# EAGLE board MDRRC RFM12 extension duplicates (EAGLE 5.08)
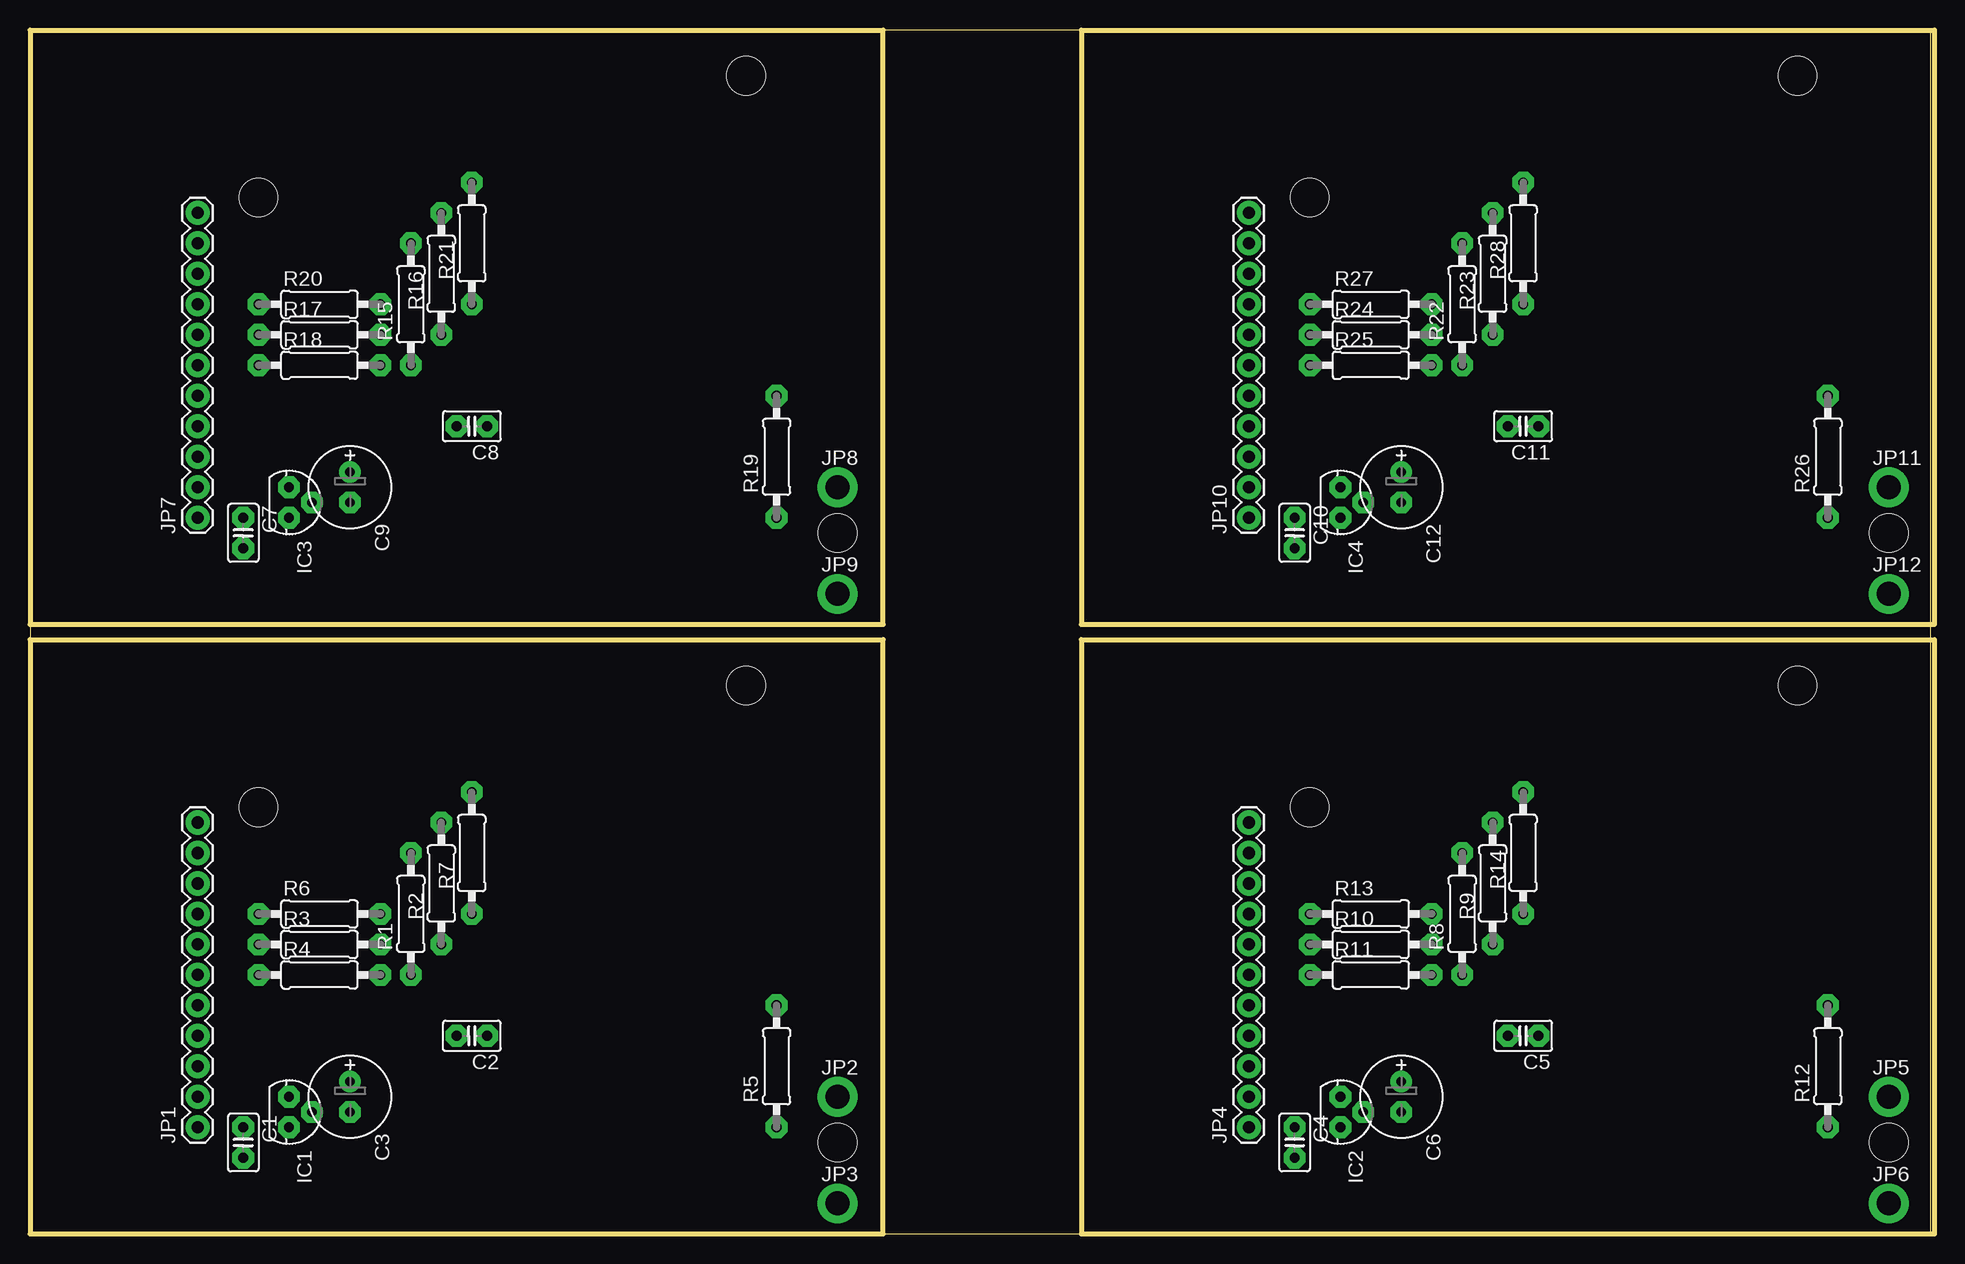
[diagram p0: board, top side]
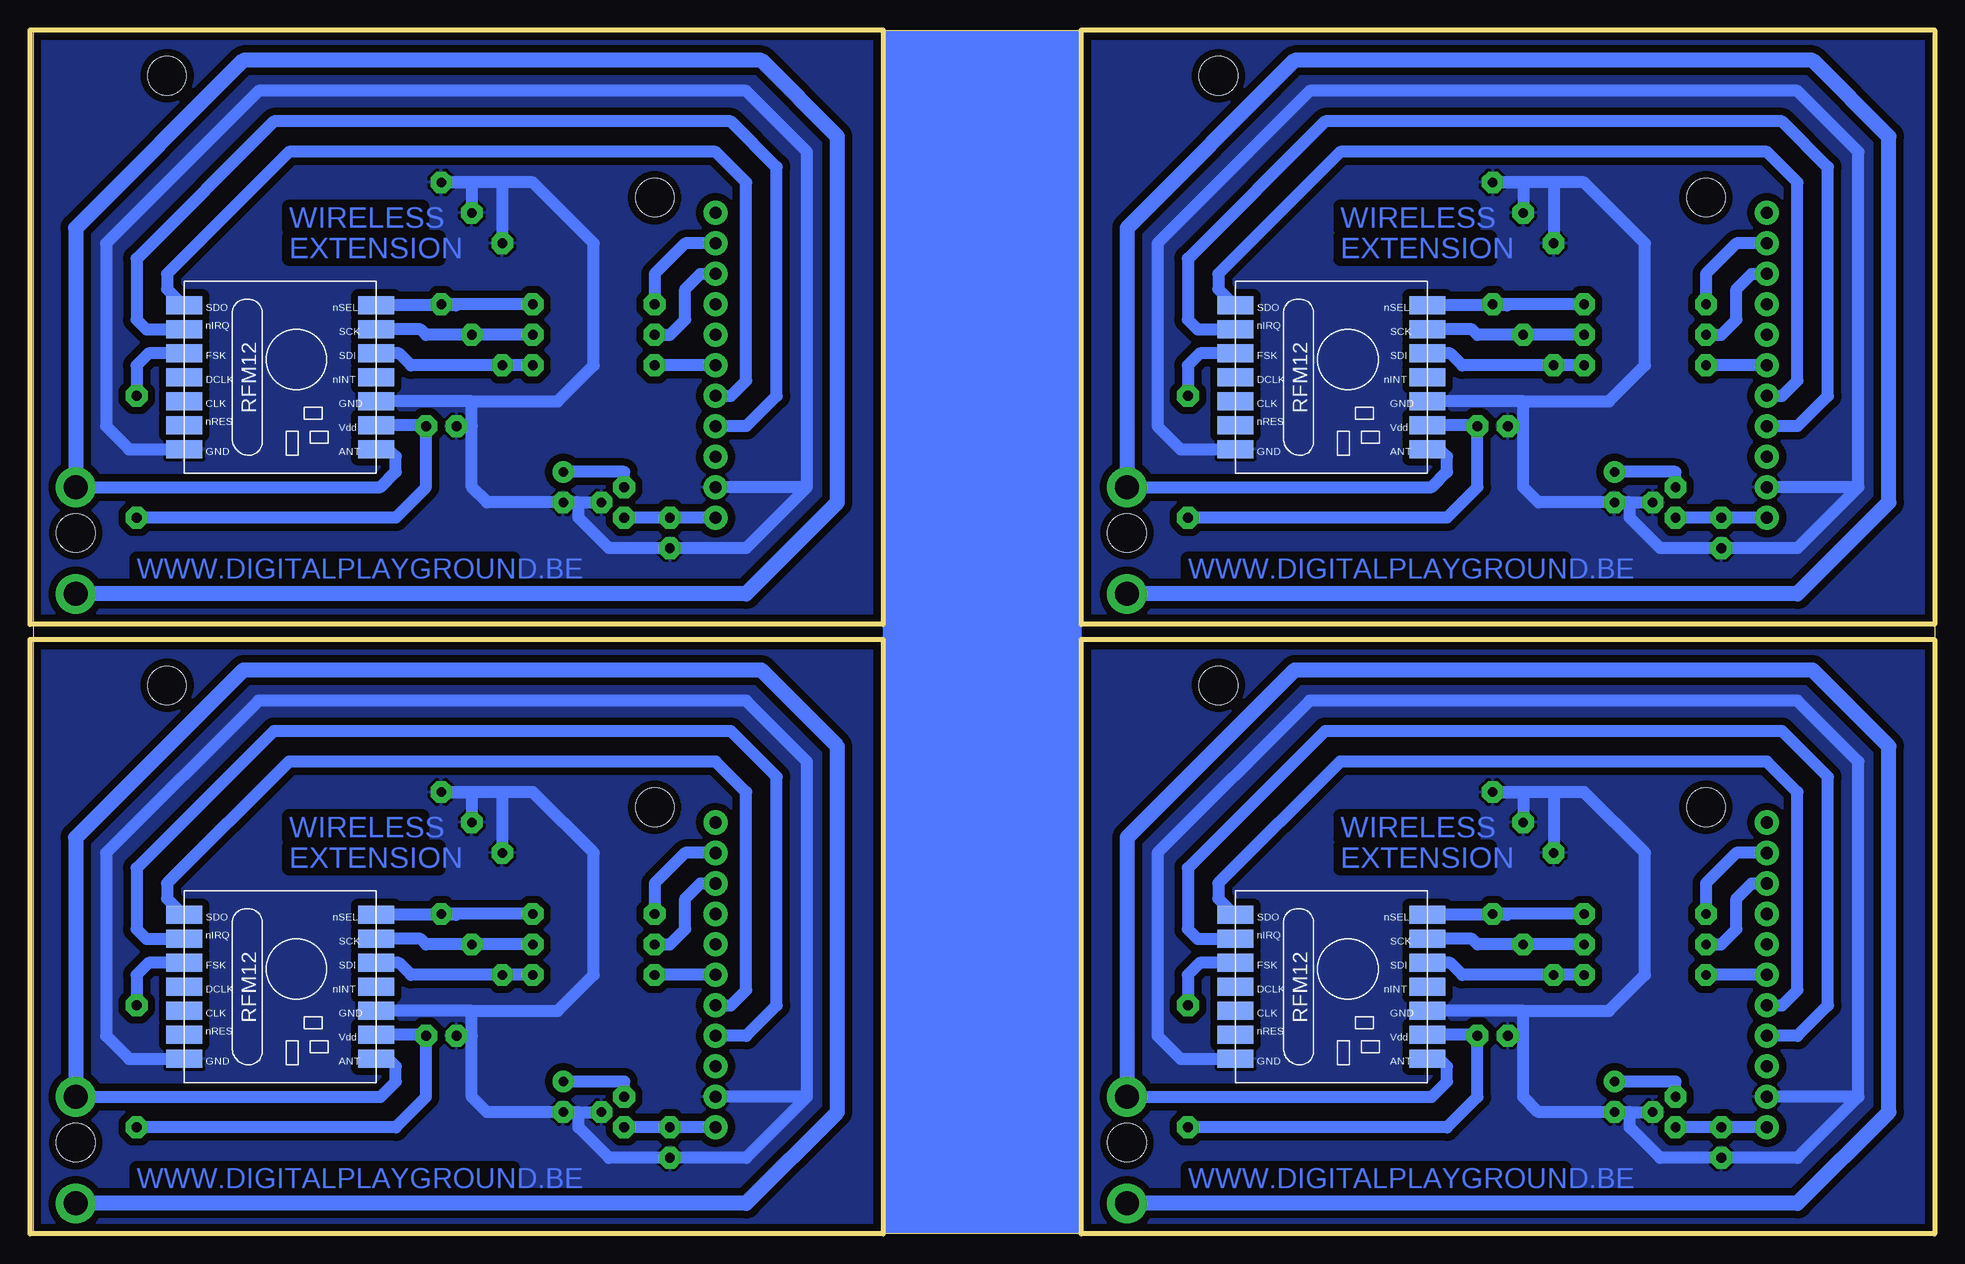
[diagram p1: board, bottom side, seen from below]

Size 158.75 x 100.33 mm. Coordinates in mm from the lower left corner, seen from the top.
Outline: 71.12,0 87.63,0
Outline: 87.63,0 158.42,0 158.42,100.32 0,100.32 0,0
Outline: 0,0 0,49.53 71.12,49.53 71.12,0
Outline: 0,0 71.12,0
Outline: 87.63,0 87.63,49.53 158.75,49.53 158.75,0 87.63,0
Outline: 0,100.33 0,50.8 71.12,50.8 71.12,100.33 0,100.33
Outline: 87.63,100.33 87.63,50.8 158.75,50.8 158.75,100.33 87.63,100.33
Copper layers (1*16): Top 0.8mm / dielectric 1.3mm / Bottom 0.8mm
Design rules "DRC settings smallest": minimum track width 0.8mm, minimum drill 24mil, track to track 0.2mm, track to pad 0.2mm, pad to pad 0.2mm, via to via 0.2mm, smd to smd 8mil, copper to edge 0.3mm, drill to drill 0.3mm, minimum pad ring 0.5mm, minimum via ring 1mm, stop-mask expansion 4mil, vias tented up to drill 0mil, thermal gap 10mil
Holes 3.2 mm at 59.69,45.72 67.31,7.62 19.05,35.56 147.32,45.72 154.94,7.62 106.68,35.56 59.69,96.52 67.31,58.42 19.05,86.36 147.32,96.52 154.94,58.42 106.68,86.36

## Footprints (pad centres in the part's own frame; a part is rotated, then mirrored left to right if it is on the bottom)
C025-025X050 = drill 0.813 octagon: 1 -1.27,0; 2 1.27,0
E2,5-7 = drill 0.813 pad 1.6 round: + -1.27,0 | drill 0.813 pad 1.6 octagon: - 1.27,0
78LXX = drill 0.813 octagon: GND 0,1.905; IN 1.27,0; OUT -1.27,0
1X11 = drill 1.016 pad 1.88 round: 1 0,0; 2 2.54,0; 3 5.08,0; 4 7.62,0; 5 10.16,0; 6 12.7,0; 7 15.24,0; 8 17.78,0; 9 20.32,0; 10 22.86,0; 11 25.4,0
1X01_2MM = drill 2 pad 3.302 round: 1 0,0
0207/10 = drill 0.813 octagon: 1 -5.08,0; 2 5.08,0
RFM12 = smd 1.5 x 3: 1 -5,-10; 2 -3,-10; 3 -1,-10; 4 1,-10; 5 3,-10; 6 5,-10; 7 7,-10; 8 7,6; 9 5,6; 10 3,6; 11 1,6; 12 -1,6; 13 -3,6; 14 -5,6

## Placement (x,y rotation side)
C1  100nF  [C025-025X050]  17.78,7.62 270 top
C2  100nF  [C025-025X050]  36.83,16.51 180 top
C3  10uF  [E2,5-7]  26.67,11.43 270 top
C4  100nF  [C025-025X050]  105.41,7.62 270 top
C5  100nF  [C025-025X050]  124.46,16.51 180 top
C6  10uF  [E2,5-7]  114.3,11.43 270 top
C7  100nF  [C025-025X050]  17.78,58.42 270 top
C8  100nF  [C025-025X050]  36.83,67.31 180 top
C9  10uF  [E2,5-7]  26.67,62.23 270 top
C10  100nF  [C025-025X050]  105.41,58.42 270 top
C11  100nF  [C025-025X050]  124.46,67.31 180 top
C12  10uF  [E2,5-7]  114.3,62.23 270 top
IC1  78L33  [78LXX]  21.59,10.16 270 top
IC2  78L33  [78LXX]  109.22,10.16 270 top
IC3  78L33  [78LXX]  21.59,60.96 270 top
IC4  78L33  [78LXX]  109.22,60.96 270 top
JP1  M11PTH  [1X11]  13.97,8.89 90 top
JP2  M01PTH_2MM  [1X01_2MM]  67.31,11.43 0 top
JP3  M01PTH_2MM  [1X01_2MM]  67.31,2.54 0 top
JP4  M11PTH  [1X11]  101.6,8.89 90 top
JP5  M01PTH_2MM  [1X01_2MM]  154.94,11.43 0 top
JP6  M01PTH_2MM  [1X01_2MM]  154.94,2.54 0 top
JP7  M11PTH  [1X11]  13.97,59.69 90 top
JP8  M01PTH_2MM  [1X01_2MM]  67.31,62.23 0 top
JP9  M01PTH_2MM  [1X01_2MM]  67.31,53.34 0 top
JP10  M11PTH  [1X11]  101.6,59.69 90 top
JP11  M01PTH_2MM  [1X01_2MM]  154.94,62.23 0 top
JP12  M01PTH_2MM  [1X01_2MM]  154.94,53.34 0 top
R1  2K2  [0207/10]  31.75,26.67 90 top
R2  2K2  [0207/10]  34.29,29.21 90 top
R3  1K  [0207/10]  24.13,24.13 0 top
R4  1K  [0207/10]  24.13,21.59 0 top
R5  10K  [0207/10]  62.23,13.97 90 top
R6  1K  [0207/10]  24.13,26.67 0 top
R7  2K2  [0207/10]  36.83,31.75 90 top
R8  2K2  [0207/10]  119.38,26.67 90 top
R9  2K2  [0207/10]  121.92,29.21 90 top
R10  1K  [0207/10]  111.76,24.13 0 top
R11  1K  [0207/10]  111.76,21.59 0 top
R12  10K  [0207/10]  149.86,13.97 90 top
R13  1K  [0207/10]  111.76,26.67 0 top
R14  2K2  [0207/10]  124.46,31.75 90 top
R15  2K2  [0207/10]  31.75,77.47 90 top
R16  2K2  [0207/10]  34.29,80.01 90 top
R17  1K  [0207/10]  24.13,74.93 0 top
R18  1K  [0207/10]  24.13,72.39 0 top
R19  10K  [0207/10]  62.23,64.77 90 top
R20  1K  [0207/10]  24.13,77.47 0 top
R21  2K2  [0207/10]  36.83,82.55 90 top
R22  2K2  [0207/10]  119.38,77.47 90 top
R23  2K2  [0207/10]  121.92,80.01 90 top
R24  1K  [0207/10]  111.76,74.93 0 top
R25  1K  [0207/10]  111.76,72.39 0 top
R26  10K  [0207/10]  149.86,64.77 90 top
R27  1K  [0207/10]  111.76,77.47 0 top
R28  2K2  [0207/10]  124.46,82.55 90 top
U$1  RFM12_SMDSMD  [RFM12]  48.26,21.59 270 bottom
U$2  RFM12_SMDSMD  [RFM12]  135.89,21.59 270 bottom
U$3  RFM12_SMDSMD  [RFM12]  48.26,72.39 270 bottom
U$4  RFM12_SMDSMD  [RFM12]  135.89,72.39 270 bottom

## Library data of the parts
C1 C2 C4 C5 C7 C8 C10 C11 = rcl
C3 C6 C9 C12 R1-R28 = resistor
IC1-IC4 = v-reg
JP1-JP12 = SparkFun
U$1-U$4 = rfm_12

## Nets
+3V1: C6.+ IC2.OUT
+3V2: C9.+ IC3.OUT
+3V3: C3.+ IC1.OUT
+3V4: C12.+ IC4.OUT
+5V: C1.1 IC1.IN JP1.1
+5V1: C4.1 IC2.IN JP4.1
+5V2: C7.1 IC3.IN JP7.1
+5V3: C10.1 IC4.IN JP10.1
GND: C1.2 C2.2 C3.- IC1.GND JP1.2 R1.2 R2.2 R7.2 U$1.7 U$1.10
GND1: C4.2 C5.2 C6.- IC2.GND JP4.2 R8.2 R9.2 R14.2 U$2.7 U$2.10
GND2: C7.2 C8.2 C9.- IC3.GND JP7.2 R15.2 R16.2 R21.2 U$3.7 U$3.10
GND3: C10.2 C11.2 C12.- IC4.GND JP10.2 R22.2 R23.2 R28.2 U$4.7 U$4.10
N$1: JP2.1 JP3.1 U$1.8
N$2: JP1.10 R6.1
N$3: R5.2 U$1.3
N$4: R2.1 R3.2 U$1.13
N$5: R1.1 R4.2 U$1.12
N$6: R6.2 R7.1 U$1.14
N$7: JP1.4 U$1.2
N$8: JP1.9 R3.1
N$9: JP1.6 R4.1
N$10: JP1.5 U$1.1
N$11: JP5.1 JP6.1 U$2.8
N$12: R12.2 U$2.3
N$13: R9.1 R10.2 U$2.13
N$14: R8.1 R11.2 U$2.12
N$15: R13.2 R14.1 U$2.14
N$16: JP4.4 U$2.2
N$17: JP4.10 R13.1
N$18: JP4.9 R10.1
N$19: JP4.6 R11.1
N$20: JP4.5 U$2.1
N$21: JP8.1 JP9.1 U$3.8
N$22: R19.2 U$3.3
N$23: R16.1 R17.2 U$3.13
N$24: R15.1 R18.2 U$3.12
N$25: R20.2 R21.1 U$3.14
N$26: JP7.4 U$3.2
N$27: JP7.10 R20.1
N$28: JP7.9 R17.1
N$29: JP7.6 R18.1
N$30: JP7.5 U$3.1
N$31: JP11.1 JP12.1 U$4.8
N$32: R26.2 U$4.3
N$33: R23.1 R24.2 U$4.13
N$34: R22.1 R25.2 U$4.12
N$35: R27.2 R28.1 U$4.14
N$36: JP10.4 U$4.2
N$37: JP10.10 R27.1
N$38: JP10.9 R24.1
N$39: JP10.6 R25.1
N$40: JP10.5 U$4.1
VDD: C2.1 R5.1 U$1.9
VDD1: C5.1 R12.1 U$2.9
VDD2: C8.1 R19.1 U$3.9
VDD3: C11.1 R26.1 U$4.9

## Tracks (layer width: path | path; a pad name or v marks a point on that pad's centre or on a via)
+3V1
  Bottom 1.016: C6.+ 109.22,12.7 IC2.OUT
+3V2
  Bottom 1.016: C9.+ 21.59,63.5 IC3.OUT
+3V3
  Bottom 1.016: C3.+ 21.59,12.7 IC1.OUT
+3V4
  Bottom 1.016: C12.+ 109.22,63.5 IC4.OUT
+5V
  Bottom 1.016: IC1.IN C1.1 JP1.1
+5V1
  Bottom 1.016: IC2.IN C4.1 JP4.1
+5V2
  Bottom 1.016: IC3.IN C7.1 JP7.1
+5V3
  Bottom 1.016: IC4.IN C10.1 JP10.1
GND
  Bottom 1.016: 57.77,14.59 U$1.7 62.85,14.59 64.77,16.51 64.77,31.75 52.07,44.45 11.43,44.45 6.35,39.37 6.35,11.43 | 25.4,10.16 IC1.GND | 25.4,10.16 C3.- 33.02,10.16 34.29,11.43 34.29,16.51 | R2.2 34.29,36.83 R7.2 31.75,36.83 | 31.75,36.83 R1.2 | 34.29,16.51 C2.2 | 6.35,11.43 11.43,6.35 C1.2 22.86,6.35 25.4,8.89 25.4,10.16 | 6.35,11.43 JP1.2 | 31.75,36.83 29.21,36.83 24.13,31.75 24.13,21.59 27.13,18.59 34.29,18.59 | 34.29,18.59 U$1.10 | 34.29,16.51 34.29,18.59
  pour Bottom (isolate 0.61): 0,49.53 71.12,49.53 71.12,0 0,0
GND1
  Bottom 1.016: 145.4,14.59 U$2.7 150.48,14.59 152.4,16.51 152.4,31.75 139.7,44.45 99.06,44.45 93.98,39.37 93.98,11.43 | 113.03,10.16 IC2.GND | 113.03,10.16 C6.- 120.65,10.16 121.92,11.43 121.92,16.51 | R9.2 121.92,36.83 R14.2 119.38,36.83 | 119.38,36.83 R8.2 | 121.92,16.51 C5.2 | 93.98,11.43 99.06,6.35 C4.2 110.49,6.35 113.03,8.89 113.03,10.16 | 93.98,11.43 JP4.2 | 119.38,36.83 116.84,36.83 111.76,31.75 111.76,21.59 114.76,18.59 121.92,18.59 | 121.92,18.59 U$2.10 | 121.92,16.51 121.92,18.59
  pour Bottom (isolate 0.61): 87.63,49.53 158.75,49.53 158.75,0 87.63,0
GND2
  Bottom 1.016: 57.77,65.39 U$3.7 62.85,65.39 64.77,67.31 64.77,82.55 52.07,95.25 11.43,95.25 6.35,90.17 6.35,62.23 | 25.4,60.96 IC3.GND | 25.4,60.96 C9.- 33.02,60.96 34.29,62.23 34.29,67.31 | R16.2 34.29,87.63 R21.2 31.75,87.63 | 31.75,87.63 R15.2 | 34.29,67.31 C8.2 | 6.35,62.23 11.43,57.15 C7.2 22.86,57.15 25.4,59.69 25.4,60.96 | 6.35,62.23 JP7.2 | 31.75,87.63 29.21,87.63 24.13,82.55 24.13,72.39 27.13,69.39 34.29,69.39 | 34.29,69.39 U$3.10 | 34.29,67.31 34.29,69.39
  pour Bottom (isolate 0.61): 0,100.33 71.12,100.33 71.12,50.8 0,50.8
GND3
  Bottom 1.016: 145.4,65.39 U$4.7 150.48,65.39 152.4,67.31 152.4,82.55 139.7,95.25 99.06,95.25 93.98,90.17 93.98,62.23 | 113.03,60.96 IC4.GND | 113.03,60.96 C12.- 120.65,60.96 121.92,62.23 121.92,67.31 | R23.2 121.92,87.63 R28.2 119.38,87.63 | 119.38,87.63 R22.2 | 121.92,67.31 C11.2 | 93.98,62.23 99.06,57.15 C10.2 110.49,57.15 113.03,59.69 113.03,60.96 | 93.98,62.23 JP10.2 | 119.38,87.63 116.84,87.63 111.76,82.55 111.76,72.39 114.76,69.39 121.92,69.39 | 121.92,69.39 U$4.10 | 121.92,67.31 121.92,69.39
  pour Bottom (isolate 0.61): 87.63,100.33 158.75,100.33 158.75,50.8 87.63,50.8
N$1
  Bottom 1.016: U$1.8 41.26,14.59 40.64,13.97 40.64,12.7 41.91,11.43 JP2.1
  Bottom 1.27: JP2.1 67.31,33.02 53.34,46.99 10.16,46.99 3.81,40.64 3.81,10.16 11.43,2.54 JP3.1
N$2
  Bottom 1.016: R6.1 19.05,29.21 16.51,31.75 JP1.10
N$3
  Bottom 1.016: U$1.3 61.23,22.59 62.23,21.59 R5.2
N$4
  Bottom 1.016: U$1.13 38.56,24.59 38.1,24.13 R2.1 R3.2
N$5
  Bottom 1.016: R4.2 R1.1 39.37,21.59 40.37,22.59 U$1.12
N$6
  Bottom 1.016: U$1.14 35.64,26.59 R7.1 R6.2
N$7
  Bottom 1.016: JP1.4 11.43,16.51 8.89,19.05 8.89,38.1 12.7,41.91 50.8,41.91 62.23,30.48 62.23,25.4 61.42,24.59 U$1.2
N$8
  Bottom 1.016: R3.1 17.78,24.13 16.51,25.4 16.51,27.94 15.24,29.21 JP1.9
N$9
  Bottom 1.016: JP1.6 R4.1
N$10
  Bottom 1.016: JP1.5 12.7,19.05 11.43,20.32 11.43,36.83 13.97,39.37 49.53,39.37 59.69,29.21 59.69,27.94 58.34,26.59 U$1.1
N$11
  Bottom 1.016: U$2.8 128.89,14.59 128.27,13.97 128.27,12.7 129.54,11.43 JP5.1
  Bottom 1.27: JP5.1 154.94,33.02 140.97,46.99 97.79,46.99 91.44,40.64 91.44,10.16 99.06,2.54 JP6.1
N$12
  Bottom 1.016: U$2.3 148.86,22.59 149.86,21.59 R12.2
N$13
  Bottom 1.016: U$2.13 126.19,24.59 125.73,24.13 R9.1 R10.2
N$14
  Bottom 1.016: R11.2 R8.1 127,21.59 128,22.59 U$2.12
N$15
  Bottom 1.016: U$2.14 123.27,26.59 R14.1 R13.2
N$16
  Bottom 1.016: JP4.4 99.06,16.51 96.52,19.05 96.52,38.1 100.33,41.91 138.43,41.91 149.86,30.48 149.86,25.4 149.05,24.59 U$2.2
N$17
  Bottom 1.016: R13.1 106.68,29.21 104.14,31.75 JP4.10
N$18
  Bottom 1.016: R10.1 105.41,24.13 104.14,25.4 104.14,27.94 102.87,29.21 JP4.9
N$19
  Bottom 1.016: JP4.6 R11.1
N$20
  Bottom 1.016: JP4.5 100.33,19.05 99.06,20.32 99.06,36.83 101.6,39.37 137.16,39.37 147.32,29.21 147.32,27.94 145.97,26.59 U$2.1
N$21
  Bottom 1.016: U$3.8 41.26,65.39 40.64,64.77 40.64,63.5 41.91,62.23 JP8.1
  Bottom 1.27: JP8.1 67.31,83.82 53.34,97.79 10.16,97.79 3.81,91.44 3.81,60.96 11.43,53.34 JP9.1
N$22
  Bottom 1.016: U$3.3 61.23,73.39 62.23,72.39 R19.2
N$23
  Bottom 1.016: U$3.13 38.56,75.39 38.1,74.93 R16.1 R17.2
N$24
  Bottom 1.016: R18.2 R15.1 39.37,72.39 40.37,73.39 U$3.12
N$25
  Bottom 1.016: U$3.14 35.64,77.39 R21.1 R20.2
N$26
  Bottom 1.016: JP7.4 11.43,67.31 8.89,69.85 8.89,88.9 12.7,92.71 50.8,92.71 62.23,81.28 62.23,76.2 61.42,75.39 U$3.2
N$27
  Bottom 1.016: R20.1 19.05,80.01 16.51,82.55 JP7.10
N$28
  Bottom 1.016: R17.1 17.78,74.93 16.51,76.2 16.51,78.74 15.24,80.01 JP7.9
N$29
  Bottom 1.016: JP7.6 R18.1
N$30
  Bottom 1.016: JP7.5 12.7,69.85 11.43,71.12 11.43,87.63 13.97,90.17 49.53,90.17 59.69,80.01 59.69,78.74 58.34,77.39 U$3.1
N$31
  Bottom 1.016: U$4.8 128.89,65.39 128.27,64.77 128.27,63.5 129.54,62.23 JP11.1
  Bottom 1.27: JP11.1 154.94,83.82 140.97,97.79 97.79,97.79 91.44,91.44 91.44,60.96 99.06,53.34 JP12.1
N$32
  Bottom 1.016: U$4.3 148.86,73.39 149.86,72.39 R26.2
N$33
  Bottom 1.016: U$4.13 126.19,75.39 125.73,74.93 R23.1 R24.2
N$34
  Bottom 1.016: R25.2 R22.1 127,72.39 128,73.39 U$4.12
N$35
  Bottom 1.016: U$4.14 123.27,77.39 R28.1 R27.2
N$36
  Bottom 1.016: JP10.4 99.06,67.31 96.52,69.85 96.52,88.9 100.33,92.71 138.43,92.71 149.86,81.28 149.86,76.2 149.05,75.39 U$4.2
N$37
  Bottom 1.016: R27.1 106.68,80.01 104.14,82.55 JP10.10
N$38
  Bottom 1.016: R24.1 105.41,74.93 104.14,76.2 104.14,78.74 102.87,80.01 JP10.9
N$39
  Bottom 1.016: JP10.6 R25.1
N$40
  Bottom 1.016: JP10.5 100.33,69.85 99.06,71.12 99.06,87.63 101.6,90.17 137.16,90.17 147.32,80.01 147.32,78.74 145.97,77.39 U$4.1
VDD
  Bottom 1.016: U$1.9 38.18,16.59 C2.1 38.1,11.43 40.64,8.89 R5.1
VDD1
  Bottom 1.016: U$2.9 125.81,16.59 C5.1 125.73,11.43 128.27,8.89 R12.1
VDD2
  Bottom 1.016: U$3.9 38.18,67.39 C8.1 38.1,62.23 40.64,59.69 R19.1
VDD3
  Bottom 1.016: U$4.9 125.81,67.39 C11.1 125.73,62.23 128.27,59.69 R26.1
(copper drawn outside any net)
  shapes: Bottom area x1

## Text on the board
Bottom: WIRELESS | WIRELESS | EXTENSION | EXTENSION | WWW.DIGITALPLAYGROUND.BE | WWW.DIGITALPLAYGROUND.BE | WIRELESS | WIRELESS | EXTENSION | EXTENSION | WWW.DIGITALPLAYGROUND.BE | WWW.DIGITALPLAYGROUND.BE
